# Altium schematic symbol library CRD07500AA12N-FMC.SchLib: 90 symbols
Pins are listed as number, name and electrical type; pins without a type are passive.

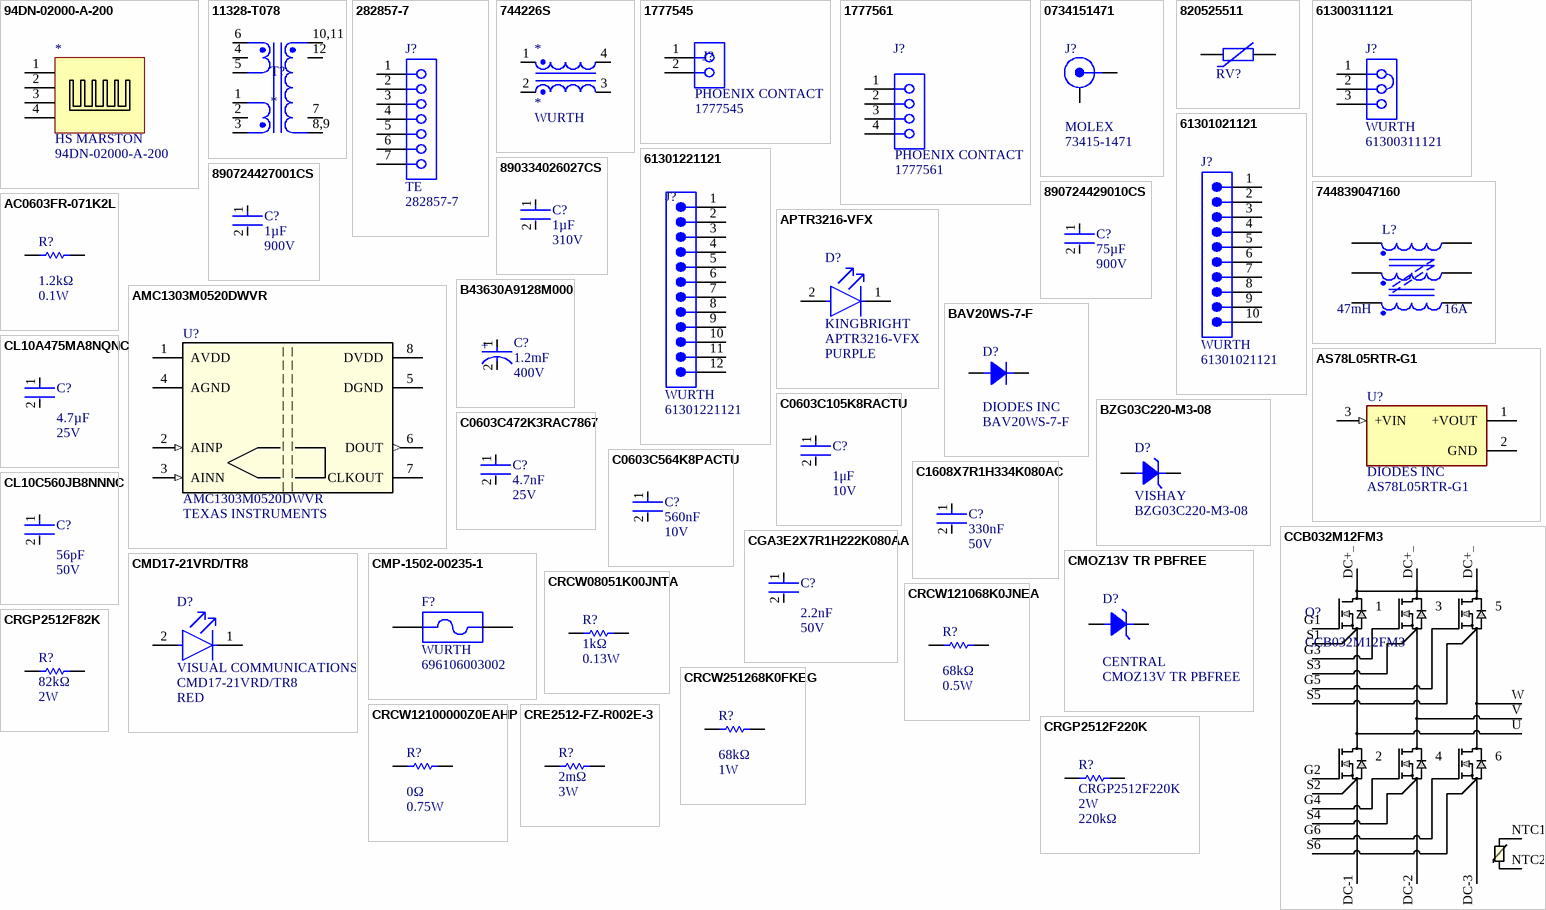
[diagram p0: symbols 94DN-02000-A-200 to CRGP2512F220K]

## 94DN-02000-A-200
designator *  Manufacturer: HS MARSTON  (hidden comment: 94DN-02000-A-200)
Heat Sink, Extruded Range - 4, Black Anodized, 0.7 C/w, 40 Mm, 123 Mm, 200 Mm Rohs Compliant: Yes; Natural Thermal Resistance: 0.7°C/W
footprint 94DN-02000-A-200
pins: 1, 2, 3, 4

## 11328-T078
designator T?
Sumida 11328-T078 flyback transformer / 600V, 670uH primary / 8:1:1
footprint 11328-T078 (Sumida 11328-T078 Flyback transformer)
pins: 1 P1, 2 NC1, 3 P1*, 4 NC0, 5 P0, 6 P0*, 7 NC2, 8,9 S, 10,11 S*, 12 NC3

## 282857-7
designator J?  Manufacturer: TE  (hidden comment: 282857-7)
Conn Terminal Block 7 POS 5.08mm Solder ST Thru-Hole; Plating: Brass; Current Rating: 24A; Voltage Rating: 300V; Number of Positions: 7; Number of Levels: 1; Connector Type: Receptacle; Closed End: No (Without); Interlock: Yes (With); Wire Gauge (Max): 30AWG; Thread Size: M3; Tail Length: 3.5mm
footprint TE_282857-7
pins: 1, 2, 3, 4, 5, 6, 7

## 744226S
designator *  Manufacturer Print: WURTH
Common Mode Chokes Dual 10uH 920Ohm 1kHz 1.6A 80mOhm DCR SMD T/R; Manufacturer: WURTH ELECTRONIK; Manufacturer Part Number: 744226S; Tolerance: 30%; Voltage Rating: 80V; Resistance: 80mR; Impedance: 920R; Number of Lines: 2
footprint WE-SL2 (SMD Inductor, 4-Leads, Body 6.3 x 9.5 mm)
pins: 1, 2, 3, 4

## 1777545
designator J?  Manufacturer: PHOENIX CONTACT  (hidden comment: 1777545)
Conn PC Terminal Block 2 POS 6.35mm Solder ST Thru-Hole 41A Cardboard; Voltage Rating: 1kV; Voltage: 600V; Number of Levels: 1; Number of Positions Per Level: 2; Current: 30A; Gender: Male; Connector Type: Screw; Wire Gauge (Max): 30AWG; Wire Gauge (Min): 10AWG; Approvals: cULus,EAC
footprint 1777545
pins: 1, 2

## 1777561
designator J?  Manufacturer: PHOENIX CONTACT  (hidden comment: 1777561)
Conn Terminal Block 4 POS 6.35mm Solder ST Thru-Hole 41A; Number of Positions: 4; Voltage Rating: 1kV; Number of Levels: 1; Current: 30A; Voltage: 600V; Wire Gauge (Max): 30AWG; Wire Gauge (Min): 10AWG
footprint 1777561
pins: 1, 2, 3, 4

## 0734151471
designator J?  Manufacturer: MOLEX  Manufacturer Part Number: 73415-1471  (hidden comment: 0734151471)
Conn.; RF/Coaxial; MMCX; Jack; Vertical; PCB; 50 Ohms; Rt. Angle; Gold Plate; Body Material: Brass; Impedance: 50R; Connector Type: PCB,MMCX,Coaxial; Max Frequency: 6GHz; Gender: Female
footprint FP-73415-1471-MFG
pins: 1 CENTER, 2,3,4,5 SHIELD

## 820525511
designator RV?, comment 550VAC, 745VDC  (value not drawn)
WE-VD Disk Varistor, THT, 550VAC, 745VDC, 430pF; Manufacturer Part Number: 820525511; Manufacturer: Wurth Elektronik; Clamping Voltage: 1500V; Energy Absorption: 408J; Operating Voltage (AC): 550V; Operating Voltage (DC): 745V; Pitch: 3.4mm; Power Dissipation: 1W; (Reverse) Breakdown Voltage: 910V; (Reverse) Peak Pulse Current: 6500A
footprint D23W10.1H27P3.4
pins: 1, 2

## 61300311121
designator J?  Manufacturer: WURTH  (hidden comment: 61300311121)
CONN HEADER 3 POS 2.54; Number of Positions: 3; Gender: Male; Connector Type: Male Pin; Pitch: 0.1inch
footprint 61300311121 (Pin Header, pitch 2.54 mm, THT, Vertical, single row, 3p)
pins: 1, 2, 3

## 61301021121
designator J?  Manufacturer: WURTH  (hidden comment: 61301021121)
THT Vertical Pin Header WR-PHD, Pitch 2.54 mm, Dual Row, 10 pins; Current Rating: 3A; Voltage Rating: 250V; Insulation: Insulated; Number of Positions: 10; Insulation Resistance: 1GR; Gender: Male; Pitch: 2.54mm; Row Spacing: 0.1inch
footprint 61301021121 (Pin Header, pitch 2.54 mm, THT, Vertical, dual row, 10p)
pins: 1, 2, 3, 4, 5, 6, 7, 8, 9, 10

## 61301221121
designator J?  Manufacturer Print: WURTH  (hidden comment: 61301221121)
CONN HEADER VERT 12POS 2.54MM; Manufacturer: WURTH ELEKTRONIK; Number of Positions: 12; Gender: Male; Voltage Rating: 250V; Pitch: 0.1inch
footprint FP-61301221121-MFG
pins: 1, 2, 3, 4, 5, 6, 7, 8, 9, 10, 11, 12

## 744839047160
designator L?, comment Rated Current: 16A  (hidden comment: 47mH)
WE-TPB HV THT Three-Phase Common Mode Power Line Choke, Type 4XL, 47mH, 16A, 14mΩ; Manufacturer Part Number: 744839047160; Manufacturer: Wurth Elektronik; Insulation Test Voltage (AC): 3000V; Material: MnZn; Rated Voltage (AC): 760V
footprint WE-TPB HV_Type 4XL_744839047160 (Three-Phase Common Mode Power Line Choke, 6-Leads, body diameter 70mm)
pins: 1, 2, 3, 4, 5, 6

## 890334026027CS
designator C?  Capacitance: 1µF  Voltage Rating (AC): 310V  (hidden comment: 890334026027CS)
WCAP-FTXX Film Capacitor 1uF 310Vac; Manufacturer: Wurth Electronics; Dielectric Material: PP; Tolerance: 10%; Ratings: X2
footprint WCAP-FTXX_L26W11H20_CS (Film Capacitors, 26x11x20mm)
pins: 1, 2

## 890724427001CS
designator C?  Capacitance: 1µF  Rated Voltage (DC): 900V  (hidden comment: 890724427001CS)
WCAP-FTDB DC-Link Capacitor, THT, L32 x W9 x H18mm, 1µF, 900V; Manufacturer: WURTH; Dissipation Factor @1kHz: 0.09%; Insulation Resistance: 10GΩ; Pitch: 27.5mm; Rate of Voltage Rise: 70V/µs; Technical Reference: MDBP275105J900DCPP15020
footprint WCAP-FTDB_L32W9H18
pins: 1, 2

## 890724429010CS
designator C?, comment Capacitance: 75µF  Rated Voltage (DC): 900V  (hidden comment: 75µF, 900V)
WCAP-FTDB DC-Link Capacitor, THT, L57 x W45 x H65mm, 75µF, 900V; Manufacturer Part Number: 890724429010CS; Manufacturer: Wurth Elektronik; Dissipation Factor @1kHz: 0.31%; Insulation Resistance: 133.33MΩ; Pitch: 52.5mm; Rate of Voltage Rise: 15V/µs; Technical Reference: MDBP525756J900DCPP15040
footprint WCAP-FTDB_L57W45H65
pins: 1, 2

## AC0603FR-071K2L
designator R?  Resistance: 1.2kΩ  Power Rating: 0.1W  (hidden comment: AC0603FR-071K2L)
Res Thick Film 0603 1.2K Ohm 1% 0.1W(1/10W) ±100ppm/°C Pad SMD Automotive T/R; Manufacturer: YAGEO; Max Power Dissipation: 100mW; Voltage Rating: 50V
footprint FP-MCR03-IPC_B
pins: 1, 2

## AMC1303M0520DWVR
designator U?  Manufacturer: TEXAS INSTRUMENTS  (hidden comment: AMC1303M0520DWVR)
1-Channel Single ADC Delta-Sigma 20Msps 16-bit Serial CMOS 8-Pin SOIC T/R; Number of Inputs: 1
footprint DWV0008A
pins: 1 AVDD (power), 2 AINP (in), 3 AINN (in), 4 AGND (power), 5 DGND (power), 6 DOUT (out), 7 CLKOUT, 8 DVDD (power)

## APTR3216-VFX
designator D?  Manufacturer Print: KINGBRIGHT  Manufacturer Part Number: APTR3216-VFX  Color: PURPLE  (hidden comment: *)
3.2X1.6MM Purple SMD Led (X=0.19, Y=0.05), Rohs
footprint FP-APTR3216SECK-MFG
pins: 1 C, 2 A

## AS78L05RTR-G1
designator U?  Manufacturer: DIODES INC  (hidden comment: AS78L05RTR-G1)
100mA 5V Linear Voltage Regulator SOT89; Max Power Dissipation: 750mW; Dropout Voltage: 1.8V; Number of Outputs: 1; Max Input Voltage: 30V; Polarity: Positive; Quiescent Current: 3mA; Accuracy: 5%; Output Type: Fixed
footprint SOT-89_4P5X2P45_DIO
pins: 1 +VOUT (power), 2 GND (power), 3 +VIN (in)

## B43630A9128M000
designator C?  Capacitance: 1.2mF  Voltage Rating: 400V  (hidden comment: B43630A9128M000)
CAP ALUM 1200UF 20% 400V SNAP; Manufacturer: TDK EPCOS; Polarity: Polar; ESR (Equivalent Series Resistance): 100mR; Life (Hours): 2000Hour; Impedance: 170mR
footprint B43630A9128M000 (400V 1200uF)
pins: 1, 2

## BAV20WS-7-F
designator D?  Manufacturer: DIODES INC  (hidden comment: BAV20WS-7-F)
VR=150V IF=200mA Trr=50ns P=200mW; Type: DEV; Forward Current: 200mA; Reverse Recovery Time: 50ns; Max Repetitive Reverse Voltage (Vrrm): 200V; Element Configuration: Single; Max Reverse Current: 100nA; Forward Voltage: 1.25V; Peak Non-Repetitive Surge Current: 2.5A; Power Dissipation: 200mW; Polarity: Standard; Capacitance: 5pF; Max Reverse Voltage (DC): 150V
footprint SOD323_DIO
pins: 1, 2

## BZG03C220-M3-08
designator D?  Manufacturer: VISHAY  (hidden comment: BZG03C220-M3-08)
BZG03 Series 220 V 0.5 A 1.25 W Surface Mount Zener Diode - DO-214AC; Zener Voltage: 220V; Tolerance: 5.68%; Max Power Dissipation: 1.25W; Impedance: 750R
footprint FP-SMA-MFG
pins: 1 11, 2 12

## C0603C105K8RACTU
designator C?  Capacitance: 1μF  Voltage Rating (DC): 10V  (hidden comment: C0603C105K8RACTU)
Cap Ceramic 1uF 10V X7R 10% SMD 0603 125C T/R; Manufacturer: KEMET; Dissipation Factor: 5%
footprint FP-C0603C-CF-IPC_B
pins: 1, 2

## C0603C472K3RAC7867
designator C?  Capacitance: 4.7nF  Voltage Rating: 25V  (hidden comment: C0603C472K3RAC7867)
CAP CER 4700PF 25V 10% X7R 0603; Manufacturer: KEMET; Manufacturer Part Number: C0603C472K3RACTU; Dielectric Material: Ceramic; Value: 4.7nF
footprint FP-C0603C-CF-IPC_B
pins: 1, 2

## C0603C564K8PACTU
designator C?  Capacitance: 560nF  Voltage Rating (DC): 10V  (hidden comment: C0603C564K8PACTU)
C0603C 560nF Ceramic Multilayer Capacitor; 10 VDC; +85degC; X5R Dielec; +/-10%; Manufacturer: KEMET; Tolerance: 10%
footprint FP-C0603C-CF-IPC_B
pins: 1, 2

## C1608X7R1H334K080AC
designator C?  Capacitance: 330nF  Voltage: 50V  (hidden comment: C1608X7R1H334K080AC)
Multilayer Ceramic Capacitor, 0.33 uF, 50 V, ± 10%, X7R, 0603 [1608 Metric]; Manufacturer: TDK
footprint FP-C0603C-CF-IPC_B
pins: 1, 2

## CCB032M12FM3
designator Q?
No Description Available; Mfr_Name: Cree Wolfspeed; Type: DEV
footprint FM3_SIX-PACK_3PHASE_CRW
pins: DC+_1, DC+_2, DC+_3, DC-1, DC-2, DC-3, G1, G2, G3, G4, G5, G6, NTC1, NTC2, S1, S2, S3, S4, S5, S6, U, V, W

## CGA3E2X7R1H222K080AA
designator C?  Capacitance: 2.2nF  Voltage Rating: 50V  (hidden comment: CGA3E2X7R1H222K080AA)
CAP CER 2200PF 50V X7R 0603; Manufacturer: TDK; Tolerance: 10%; Value: 2.2nF
footprint FP-GCM188-0_1-IPC_A
pins: 1, 2

## CL10A475MA8NQNC
designator C?  Capacitance: 4.7µF  Voltage Rating: 25V  (hidden comment: CL10A475MA8NQNC)
CAP CER 4.7UF 25V X5R 0603; Manufacturer: Samsung; Tolerance: 20%
footprint FP-C0603C-CF-IPC_B
pins: 1, 2

## CL10C560JB8NNNC
designator C?  Capacitance: 56pF  Voltage Rating: 50V  (hidden comment: CL10C560JB8NNNC)
CAP CER 56PF 50V C0G/NP0 0603; Manufacturer: SAMSUNG; Material: Ceramic; Tolerance: 5%; Dielectric: C0G; Temperature Coefficient: 30ppm/°C
footprint FP-C0603C-CF-IPC_B
pins: 1, 2
1 alternate drawing of the same symbol

## CMD17-21VRD/TR8
designator D?  value RED  Manufacturer: VISUAL COMMUNICATIONS  Manufacturer Part Number: CMD17-21VRD/TR8  (hidden comment: *)
LED RED DIFFUSED 0805 SMD; Power Rating: 100mW; Luminous Intensity: 6mcd; Viewing Angle: 140°; Lens Style: Diffused,Tinted,Rectangular,Colored; Forward Current: 20mA; Forward Voltage: 2V; Wavelength: 640nm; Reverse Voltage (DC): 5V; Number of LEDs: 1
footprint FP-LTST-C171GKT-MFG-RED
pins: 1 C, 2 A

## CMOZ13V TR PBFREE
designator D?  Manufacturer: CENTRAL  (hidden comment: CMOZ13V TR PBFREE)
DIODE ZENER 13V 300MW SOD523; Description: Diode Zener Single 13V 5% 350mW 2-Pin SOD-523 T/R; Tolerance: 5%; Impedance: 30R
footprint DIODE_SOD-523_1P2XP8_CNS
pins: 1, 2

## CMP-1502-00235-1
designator F?, comment Manufacturer: WURTH  (hidden comment: 696106003002)
WR-FSH Fuse Holder Blocks Fuse Holder Blocks Clip Cover for PCB; Fuse Size: 5x20mm
footprint 696106003002 (FUSEHOLDER BLOCKS - PCB - CLIP COVER - THT)
pins: 1, 2

## CRCW08051K00JNTA
designator R?  Resistance: 1kΩ  Power Rating: 0.13W  (hidden comment: *)
Resistor, Thick Film Chip; 1 K Ohms; Case 0805; 0.125W; +/-5%; SMD; 200ppm/K; 150V; Manufacturer: Vishay Dale; Manufacturer Part Number: CRCW08051K00JNTA; Tolerance: 5%; Temperature Coefficient: 200ppm/°C; Max Power Dissipation: 125mW
footprint RESC2013X50X30LL20T20 (Chip Resistor, 2-Leads, Body 2.00x1.25mm, IPC High Density)
footprint RESC2013X50X30ML20T20 (Chip Resistor, 2-Leads, Body 2.00x1.25mm, IPC Low Density)
footprint RESC2013X50X30NL20T20 (Chip Resistor, 2-Leads, Body 2.00x1.25mm, IPC Medium Density)
pins: 1, 2

## CRCW121068K0JNEA
designator R?  Resistance: 68kΩ  Max Power Dissipation: 0.5W  (hidden comment: CRCW121068K0JNEA)
Res Thick Film 1210 68K Ohm 5% 1/2W ±200ppm/°C Molded SMD SMD Paper T/R; Manufacturer: VISHAY DALE; Power Rating: 500mW; Voltage Rating: 200V
footprint RESC3125X70X40LL20T20 (Chip Resistor, 2-Leads, Body 3.10x2.50mm, IPC High Density)
footprint RESC3125X70X40ML20T20 (Chip Resistor, 2-Leads, Body 3.10x2.50mm, IPC Low Density)
footprint RESC3125X70X40NL20T20 (Chip Resistor, 2-Leads, Body 3.10x2.50mm, IPC Medium Density)
pins: 1, 2

## CRCW251268K0FKEG
designator R?  Resistance: 68kΩ  Power Rating: 1W  (hidden comment: CRCW251268K0FKEG)
Res Thick Film 2512 68K Ohm 1% 1W ±100ppm/°C Molded SMD SMD Blister T/R; Manufacturer: VISHAY DALE; Voltage Rating (DC): 500V
footprint FP-RC2512-0_65-IPC_A
footprint FP-RC2512-0_65-IPC_B
footprint FP-RC2512-0_65-IPC_C
footprint FP-RC2512-0_65-MFG
pins: 1, 2

## CRCW12100000Z0EAHP
designator R?  Resistance: 0Ω  Power Rating: 0.75W  (hidden comment: CRCW12100000Z0EAHP)
RES SMD 0 OHM JUMPER 3/4W 1210; Manufacturer: VISHAY; Max Power Dissipation: 750mW
footprint RESC3125X70X40NL20T20 (Chip Resistor, 2-Leads, Body 3.10x2.50mm, IPC Medium Density)
pins: 1, 2

## CRE2512-FZ-R002E-3
designator R?  Resistance: 2mΩ  Power Rating: 3W  (hidden comment: CRE2512-FZ-R002E-3)
Res Thick Film 2512 0.002 Ohm 1% 3W ±50ppm/C Pad SMD Automotive T/R; Manufacturer: BOURNS; Temperature Coefficient: 75ppm/°C
footprint FP-RC2512-0_65-MFG
pins: 1, 2

## CRGP2512F82K
designator R?  value 82kΩ  Power: 2W  (hidden comment: CRGP2512F82K)
Res Thick Film 2512 82K Ohm 1% 2W ±100ppm/C Pad SMD T/R; Manufacturer: TE
footprint FP-CRGP2512-IPC_A
footprint FP-CRGP2512-IPC_B
footprint FP-CRGP2512-IPC_C
pins: 1, 2

## CRGP2512F220K
designator R?  Power Rating: 2W  Resistance: 220kΩ
CRGP2512 220KΩ 2W ±100ppm/°C 1% 500V; Manufacturer: TE; Tolerance: 0.01
footprint FP-CRGP2512-IPC_C
footprint FP-CRGP2512-IPC_A
footprint FP-CRGP2512-IPC_B
pins: 1, 2

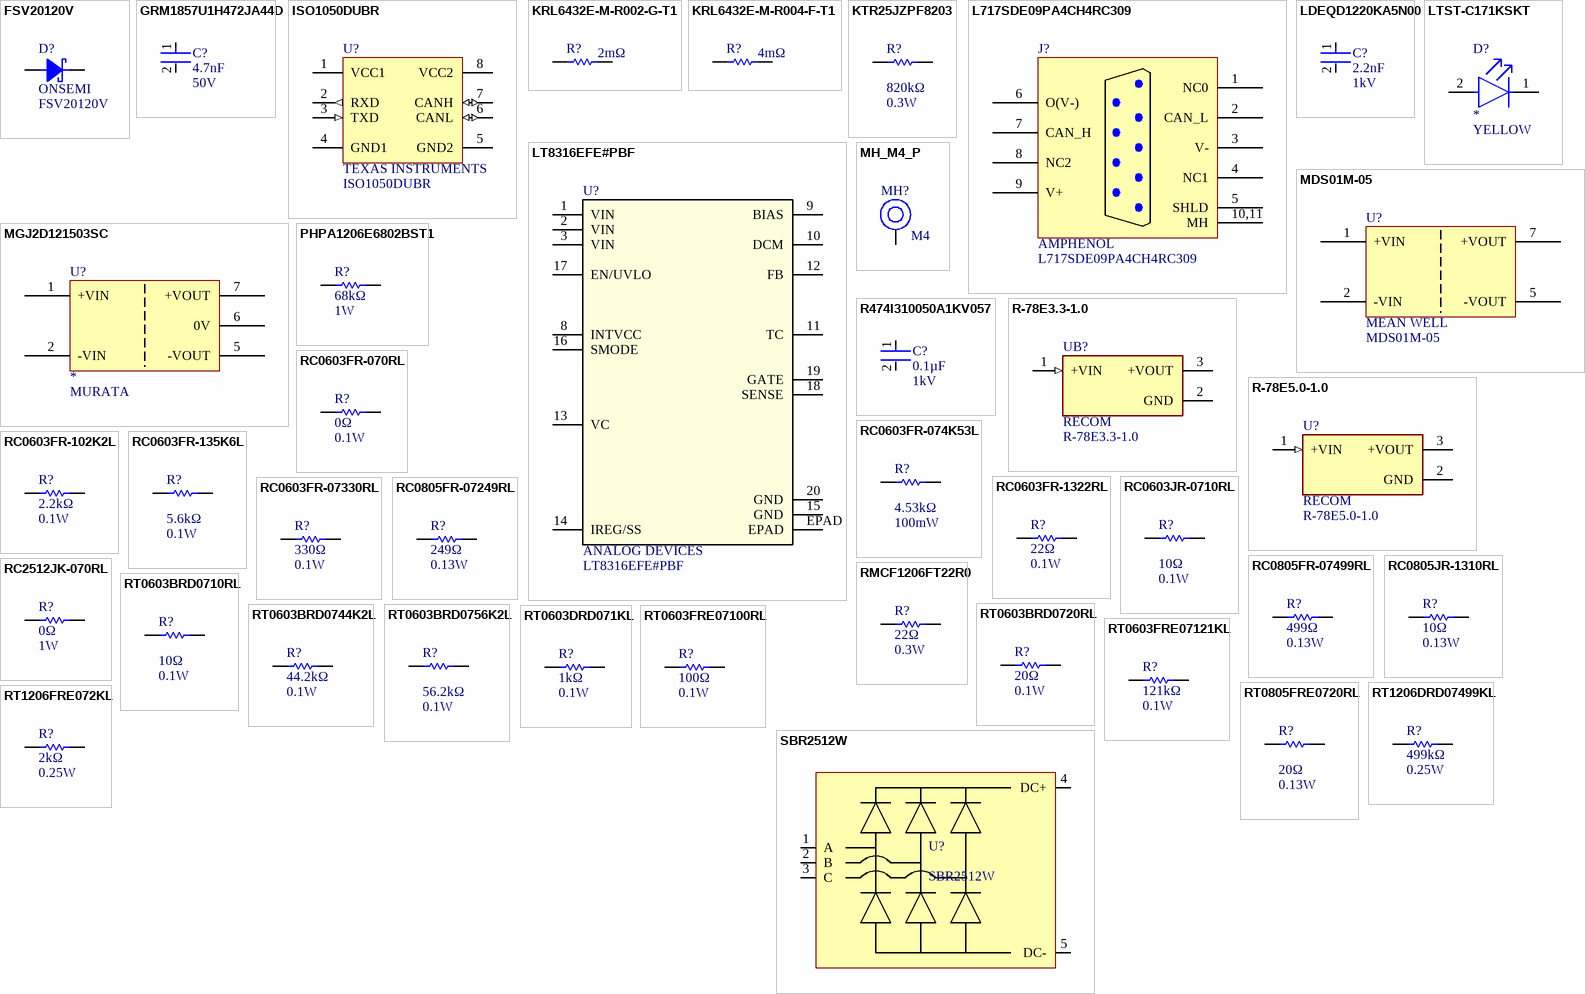
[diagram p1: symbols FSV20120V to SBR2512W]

## FSV20120V
designator D?  Manufacturer: ONSEMI  (hidden comment: FSV20120V)
Diode Schottky Rectifier 120V 20A 3-Pin TO-277 T/R; Element Configuration: Single; Max Forward Surge Current (Ifsm): 270A
footprint SOT_20100V_ONS
pins: 1,2, 3

## GRM1857U1H472JA44D
designator C?  Capacitance: 4.7nF  Voltage Rating (DC): 50V  (hidden comment: GRM1857U1H472JA44D)
Cap Ceramic 0.0047uF 50V U2J 5% SMD 0603 125°C Paper T/R; Manufacturer: MURATA
footprint FP-C0603C-CF-IPC_B
pins: 1, 2

## ISO1050DUBR
designator U?  Manufacturer: TEXAS INSTRUMENTS  (hidden comment: ISO1050DUBR)
Isolated CAN Transceiver, -55 to 105 degC, 8-pin SOP (DUB), Green (RoHS & no Sb/Br); Rating: Catalog; Isolated: Yes; Drivers Per Package: 1
footprint DUB0008A_M (SOP, 8-Leads, Body 6.7x9.6mm, Pitch 2.54mm, IPC Low Density)
footprint DUB0008A_L (SOP, 8-Leads, Body 6.7x9.6mm, Pitch 2.54mm, IPC High Density)
footprint DUB0008A_N (SOP, 8-Leads, Body 6.7x9.6mm, Pitch 2.54mm, IPC Medium Density)
pins: 1 VCC1 (power), 2 RXD (out), 3 TXD (in), 4 GND1 (power), 5 GND2 (power), 6 CANL (io), 7 CANH (io), 8 VCC2 (power)

## KRL6432E-M-R002-G-T1
designator R?  Resistance: 2mΩ  (hidden comment: KRL6432E-M-R002-G-T1)
Metal Foil Low Resistance Chip Resistor (long-side terminal), 2512, RoHS; Manufacturer: Susumu; Tolerance: 2%; Power Rating: 3W; Temperature Coefficient: 100ppm/°C
footprint RESC310X630X70N
pins: 1, 2

## KRL6432E-M-R004-F-T1
designator R?  Resistance: 4mΩ  (hidden comment: KRL6432E-M-R004-F-T1)
Metal Foil Low Resistance Chip Resistor (long-side terminal), 2512, RoHS; Manufacturer: Susumu; Tolerance: 1%; Power Rating: 3W; Temperature Coefficient: 50ppm/°C
footprint RESC310X630X70N
pins: 1, 2

## KTR25JZPF8203
designator R?  Resistance: 820kΩ  Max Power Dissipation: 0.3W  (hidden comment: KTR25JZPF8203)
Res Thick Film 1210 820K Ohm 1% 0.33W(1/3W) ±100ppm/C Pad SMD Automotive T/R; Manufacturer: ROHM; Temperature Coefficient: 100ppm/°C
footprint RESC3125X70X40LL20T20 (Chip Resistor, 2-Leads, Body 3.10x2.50mm, IPC High Density)
footprint RESC3125X70X40ML20T20 (Chip Resistor, 2-Leads, Body 3.10x2.50mm, IPC Low Density)
footprint RESC3125X70X40NL20T20 (Chip Resistor, 2-Leads, Body 3.10x2.50mm, IPC Medium Density)
pins: 1, 2

## L717SDE09PA4CH4RC309
designator J?  Manufacturer: AMPHENOL  (hidden comment: L717SDE09PA4CH4RC309)
CONN D-SUB PLUG 9POS R/A SLDR; Number of Terminals/Pins: 9; Connector Type: D-Sub,Plug; Voltage Rating: 250V; Current Rating: 5A; Number of Ports: 1; Pitch: 2.74mm
footprint L717SDE09PA4CH4RC309 (CONN D-SUB PLUG 9POS R/A SLDR)
pins: 1 NC0, 2 CAN_L, 3 V-, 4 NC1, 5 SHLD, 6 O(V-), 7 CAN_H, 8 NC2, 9 V+, 10,11 MH

## LDEQD1220KA5N00
designator C?  Capacitance: 2.2nF  Voltage Rating (DC): 1kV  (hidden comment: LDEQD1220KA5N00)
Cap Film 0.0022uF 1000V PEN 10% (6 X 5 X 2mm) Stacked 125C Automotive T/R; Manufacturer: KEMET; Dielectric Material: Polyester; Voltage Rating (AC): 250V
footprint CAP_LDE_QD_1220_KEM
pins: 1, 2

## LT8316EFE#PBF
designator U?  Manufacturer: ANALOG DEVICES  (hidden comment: LT8316EFE#PBF)
DC/DC Cntrlr Single-OUT Step Down/Flyback 142kHz Automotive 16-Pin TSSOP EP Tube
footprint TSSOP20_FE_BB(16)
pins: 1 VIN, 2 VIN, 3 VIN, 8 INTVCC, 9 BIAS, 10 DCM, 11 TC, 12 FB, 13 VC, 14 IREG/SS, 15 GND, 16 SMODE, 17 EN/UVLO, 18 SENSE, 19 GATE, 20 GND, EPAD

## LTST-C171KSKT
designator D?  Color Print: YELLOW
LED YELLOW CLEAR 0805 SMD; Manufacturer: Vishay Lite-On; Manufacturer Part Number: LTST-C171KSKT; Lens Color: Colorless; Number of LEDs: 1; Reverse Voltage: 5V; Viewing Angle: 130°; Lens Style: Diffused,Colorless,Rectangular,Clear; Luminous Intensity: 50mcd; Forward Voltage: 2V; Dominant Wavelength: 587nm; Test Current: 20mA; Wavelength: 588nm; Forward Current: 30mA; Max Power Dissipation: 75mW
footprint FP-LTST-C171GKT-MFG-YELLOW
pins: 1 C, 2 A

## MDS01M-05
designator U?  Manufacturer: MEAN WELL  (hidden comment: MDS01M-05)
Module DC-DC 1-OUT 5V 20mA to 200mA 1W Through Hole 5-Pin SIP
footprint MDS01M-05
pins: 1 +VIN, 2 -VIN, 5 -VOUT, 7 +VOUT

## MGJ2D121503SC
designator U?  Manufacturer Print: MURATA
DC DC CONVERTER 15V -3V 1.7W; Manufacturer Part Number: MGJ2D121503SC
footprint MGJ2D121509SC
pins: 1 +VIN, 2 -VIN, 5 -VOUT, 6 0V, 7 +VOUT

## MH_M4_P
designator MH?  Size: M4  (hidden comment: *)
footprint MH_M4_P (M4 plated mounting hole)
pins: 1

## PHPA1206E6802BST1
designator R?  Resistance: 68kΩ  Power: 1W  (hidden comment: PHPA1206E6802BST1)
THIN FILM RES SMD 68K OHM 0.1% 1; Manufacturer: VISHAY
footprint RESC3216X65X50NL15T25 (Chip Resistor, 2-Leads, Body 3.20x1.60mm, IPC Medium Density)
pins: 1, 2

## R474I310050A1KV057
designator C?  Capacitance: 0.1µF  Voltage: 1kV  (hidden comment: R474I310050A1KV057)
0.1uF, 1KVDC, X1 rated; Manufacturer: KEMET
footprint R474I310050A1KV057 (0.1uF 1KVDC X1)
pins: 1, 2

## R-78E3.3-1.0
designator UB?  Manufacturer: RECOM  (hidden comment: R-78E3.3-1.0)
DC DC CONVERTER 3.3V 3W; Number of Outputs: 1; Min Input Voltage: 8V; Max Input Voltage: 28V; Max Output Current: 1A; Efficiency: 91%; Max Output Power: 3.3W; Min Input Voltage (DC): 7V
footprint CONV_R-78E3.3-1.0
pins: 1 +VIN (in), 2 GND (power), 3 +VOUT (power)

## R-78E5.0-1.0
designator U?  Manufacturer: RECOM  (hidden comment: R-78E5.0-1.0)
DC DC CONVERTER 5V 5W; Number of Outputs: 1; Min Input Voltage: 8V; Max Input Voltage: 28V; Max Output Current: 1A; Efficiency: 91%
footprint CONV_R-78E5.0-1.0
pins: 1 +VIN (in), 2 GND (power), 3 +VOUT (power)

## RC0603FR-070RL
designator R?  Resistance: 0Ω  Power Rating: 0.1W  (hidden comment: RC0603FR-070RL)
RC Series 0603 0.1 W 0 Ohm Jumper Surface Mount Thick Film Chip Resistor; Manufacturer: YAGEO; Tolerance: 1%; Voltage Rating (DC): 50V; Max Power Dissipation: 100mW; Temperature Coefficient: 200ppm/°C; Current Rating: 1A; Working Voltage: 75V
footprint FP-MCR03-IPC_B
pins: 1, 2

## RC0603FR-074K53L
designator R?  Resistance: 4.53kΩ  Power Rating: 100mW  (hidden comment: RC0603FR-074K53L)
Res Thick Film 0603 4.53K Ohm 1% 0.1W(1/10W) ±100ppm/C Pad SMD T/R; Manufacturer: YAGEO; Temperature Coefficient: 100ppm/°C; Voltage Rating: 50V
footprint FP-MCR03-IPC_B
pins: 1, 2

## RC0603FR-102K2L
designator R?  Resistance: 2.2kΩ  Power Rating: 0.1W  (hidden comment: RC0603FR-102K2L)
Res Thick Film 0603 2.2K Ohm 1% 1/10W 100ppm/C Molded SMD SMD Paper T/R; Manufacturer: YAGEO; Temperature Coefficient: 100ppm/°C; Voltage Rating (DC): 50V
footprint FP-MCR03-IPC_B
pins: 1, 2

## RC0603FR-135K6L
designator R?  Resistance: 5.6kΩ  Power Rating: 0.1W  (hidden comment: RC0603FR-135K6L)
Res Thick Film 0603 5.6K Ohm 1% 1/10W ±100ppm/°C Molded SMD Paper T/R; Manufacturer: YAGEO; Voltage Rating: 50V
footprint FP-MCR03-IPC_B
pins: 1, 2

## RC0603FR-1322RL
designator R?  Resistance: 22Ω  Power Rating: 0.1W  (hidden comment: RC0603FR-1322RL)
Res Thick Film 0603 22 Ohm 1% 1/10W ±100ppm/°C SMD Paper T/R; Manufacturer: Yageo; Voltage Rating: 50V
footprint FP-MCR03-IPC_B
pins: 1, 2

## RC0603FR-07330RL
designator R?  Resistance: 330Ω  Max Power Dissipation: 0.1W  (hidden comment: RC0603FR-07330RL)
YAGEO (PHYCOMP) - RC0603FR-07330RL - RES, THICK FILM, 330R, 1%, 0.1W, 0603; Temperature Coefficient: 100ppm/°C; Power Rating: 100mW; Voltage Rating: 50V
footprint FP-MCR03-IPC_B
pins: 1, 2

## RC0603JR-0710RL
designator R?  Resistance: 10Ω  Max Power Dissipation: 0.1W  (hidden comment: RC0603JR-0710RL)
Res General Purpose Thick Film 0603 10 Ohm 5% 1/10W ±200ppm/°C Molded SMD Paper T/R; Manufacturer: YAGEO; Power Rating: 100mW; Voltage Rating: 50V
footprint FP-MCR03-IPC_B
pins: 1, 2

## RC0805FR-07249RL
designator R?  Resistance: 249Ω  Power Rating: 0.13W  (hidden comment: *)
RES 249 OHM 1% 1/8W 0805; Manufacturer: YAGEO; Manufacturer Part Number: RC0805FR-07249RL; Voltage Rating: 150V; Max Power Dissipation: 125mW; Temperature Coefficient: 100ppm/°C; Value: 249Ω
footprint FP-MCR10-IPC_A
pins: 1, 2

## RC0805FR-07499RL
designator R?  Resistance: 499Ω  Max Power Dissipation: 0.13W  (hidden comment: *)
RES 499 OHM 1% 1/8W 0805; Manufacturer: YAGEO; Manufacturer Part Number: RC0805FR-07499RL; Power Rating: 125mW; Voltage Rating: 150V; Temperature Coefficient: 100ppm/°C; Value: 499Ω
footprint FP-MCR10-IPC_A
pins: 1, 2

## RC0805JR-1310RL
designator R?  Resistance: 10Ω  Power Rating: 0.13W  (hidden comment: RC0805JR-1310RL)
Res Thick Film 0805 10 Ohm 5% 1/8W ±200ppm/°C Molded SMD Paper T/R; Manufacturer: YAGEO; Voltage Rating: 150V
footprint RESC2013X60X35LL10T20 (Chip Resistor, 2-Leads, Body 2.00x1.25mm, IPC High Density)
footprint RESC2013X60X35ML10T20 (Chip Resistor, 2-Leads, Body 2.00x1.25mm, IPC Low Density)
footprint RESC2013X60X35NL10T20 (Chip Resistor, 2-Leads, Body 2.00x1.25mm, IPC Medium Density)
pins: 1, 2

## RC2512JK-070RL
designator R?  Resistance: 0Ω  Max Power Dissipation: 1W  (hidden comment: RC2512JK-070RL)
RES SMD 0 OHM JUMPER 1W 2512; Manufacturer: YAGEO; Tolerance: 5%; Temperature Coefficient: 200ppm/°C; Voltage Rating: 200V
footprint FP-RC2512-0_65-IPC_A
footprint FP-RC2512-0_65-IPC_B
footprint FP-RC2512-0_65-IPC_C
footprint FP-RC2512-0_65-MFG
pins: 1, 2

## RMCF1206FT22R0
designator R?  Resistance: 22Ω  Max Power Dissipation: 0.3W  (hidden comment: RMCF1206FT22R0)
Res Thick Film 1206 22 Ohm 1% 1/4W ±100ppm/°C Molded SMD SMD Paper T/R; Manufacturer: Stackpole Electronics
footprint FP-CSR1206-IPC_A
footprint FP-CSR1206-IPC_B
footprint FP-CSR1206-IPC_C
footprint FP-CSR1206-MFG
pins: 1, 2

## RT0603BRD0710RL
designator R?  Resistance: 10Ω  Max Power Dissipation: 0.1W  (hidden comment: RT0603BRD0710RL)
Res Thin Film 0603 10 Ohm 0.1% 0.1W(1/10W) ±25ppm/C Pad SMD T/R; Manufacturer: Yageo; Temperature Coefficient: 25ppm/°C; Power Rating: 100mW; Voltage Rating: 75V
footprint FP-MCR03-IPC_B
pins: 1, 2

## RT0603BRD0720RL
designator R?  Resistance: 20Ω  Power Rating: 0.1W  (hidden comment: RT0603BRD0720RL)
Res Thin Film 0603 20 Ohm 0.1% 1/10W ±25ppm/°C Molded SMD SMD Paper T/R; Manufacturer: YAGEO; Max Power Dissipation: 100mW; Voltage Rating: 75V; Voltage Rating (DC): 50V
footprint FP-MCR03-IPC_B
pins: 1, 2

## RT0603BRD0744K2L
designator R?  Resistance: 44.2kΩ  Max Power Dissipation: 0.1W  (hidden comment: RT0603BRD0744K2L)
Res High Precision Thin Film 0603 44.2k Ohm 0.1% 1/10W ±25ppm/°C Molded Paper T/R; Manufacturer: YAGEO; Power Rating: 100mW; Voltage Rating (DC): 50V; Voltage Rating: 75V
footprint FP-MCR03-IPC_B
pins: 1, 2

## RT0603BRD0756K2L
designator R?  Resistance: 56.2kΩ  Power Rating: 0.1W  (hidden comment: RT0603BRD0756K2L)
Res Thin Film 0603 56.2K Ohm 0.1% 1/10W ±25ppm/°C Molded SMD SMD Paper T/R; Manufacturer: YAGEO; Max Power Dissipation: 100mW; Voltage Rating: 75V; Voltage Rating (DC): 50V
footprint FP-MCR03-IPC_B
pins: 1, 2

## RT0603DRD071KL
designator R?  Resistance: 1kΩ  Power Rating: 0.1W  (hidden comment: RT0603DRD071KL)
Res Thin Film 0603 1K Ohm 0.5% 1/10W ±25ppm/°C Molded SMD SMD Paper T/R; Manufacturer: YAGEO; Max Power Dissipation: 100mW; Voltage Rating (DC): 50V; Voltage Rating: 75V
footprint FP-MCR03-IPC_B
pins: 1, 2

## RT0603FRE07100RL
designator R?  Resistance: 100Ω  Power Rating: 0.1W  (hidden comment: RT0603FRE07100RL)
RES SMD 100 OHM 1% 1/10W 0603; Manufacturer: YAGEO; Temperature Coefficient: 50ppm/°C; Voltage Rating: 75V; Max Power Dissipation: 100mW
footprint FP-MCR03-IPC_B
pins: 1, 2

## RT0603FRE07121KL
designator R?  Resistance: 121kΩ  Power Rating: 0.1W  (hidden comment: RT0603FRE07121KL)
Res Thin Film 0603 121K Ohm 1% 1/10W ±50ppm/°C Molded SMD SMD Paper T/R; Manufacturer: YAGEO; Voltage Rating (DC): 50V; Voltage Rating: 75V; Max Power Dissipation: 100mW
footprint FP-MCR03-IPC_B
pins: 1, 2

## RT0805FRE0720RL
designator R?  Resistance: 20Ω  Max Power Dissipation: 0.13W  (hidden comment: RT0805FRE0720RL)
Res Thin Film 0805 20 Ohm 1% 1/8W ±50ppm/°C Molded SMD SMD Paper T/R; Manufacturer: YAGEO; Power Rating: 125mW; Voltage Rating: 150V
footprint RESC2013X60X35LL10T20 (Chip Resistor, 2-Leads, Body 2.00x1.25mm, IPC High Density)
footprint RESC2013X60X35ML10T20 (Chip Resistor, 2-Leads, Body 2.00x1.25mm, IPC Low Density)
footprint RESC2013X60X35NL10T20 (Chip Resistor, 2-Leads, Body 2.00x1.25mm, IPC Medium Density)
pins: 1, 2

## RT1206DRD07499KL
designator R?  Resistance: 499kΩ  Max Power Dissipation: 0.25W  (hidden comment: RT1206DRD07499KL)
Res Thin Film 1206 499K Ohm 0.5% 0.25W(1/4W) ±25ppm/C Pad SMD T/R; Manufacturer: YAGEO; Temperature Coefficient: 25ppm/°C; Voltage Rating (DC): 200V
footprint FP-CSR1206-IPC_A
footprint FP-CSR1206-IPC_B
footprint FP-CSR1206-IPC_C
footprint FP-CSR1206-MFG
pins: 1, 2

## RT1206FRE072KL
designator R?  Resistance: 2kΩ  Max Power Dissipation: 0.25W  (hidden comment: RT1206FRE072KL)
Res Thin Film 1206 2K Ohm 1% 1/4W ±50ppm/°C Molded SMD SMD Paper T/R; Manufacturer: YAGEO; Power Rating: 250mW; Voltage Rating: 200V
footprint FP-CSR1206-IPC_A
footprint FP-CSR1206-IPC_B
footprint FP-CSR1206-IPC_C
footprint FP-CSR1206-MFG
pins: 1, 2

## SBR2512W
designator U?
BRIDGE RECT 3P 1.2KV 25A
footprint SBR2512W (3P diode bridge 1200V 25A)
pins: 1 A, 2 B, 3 C, 4 DC+, 5 DC-

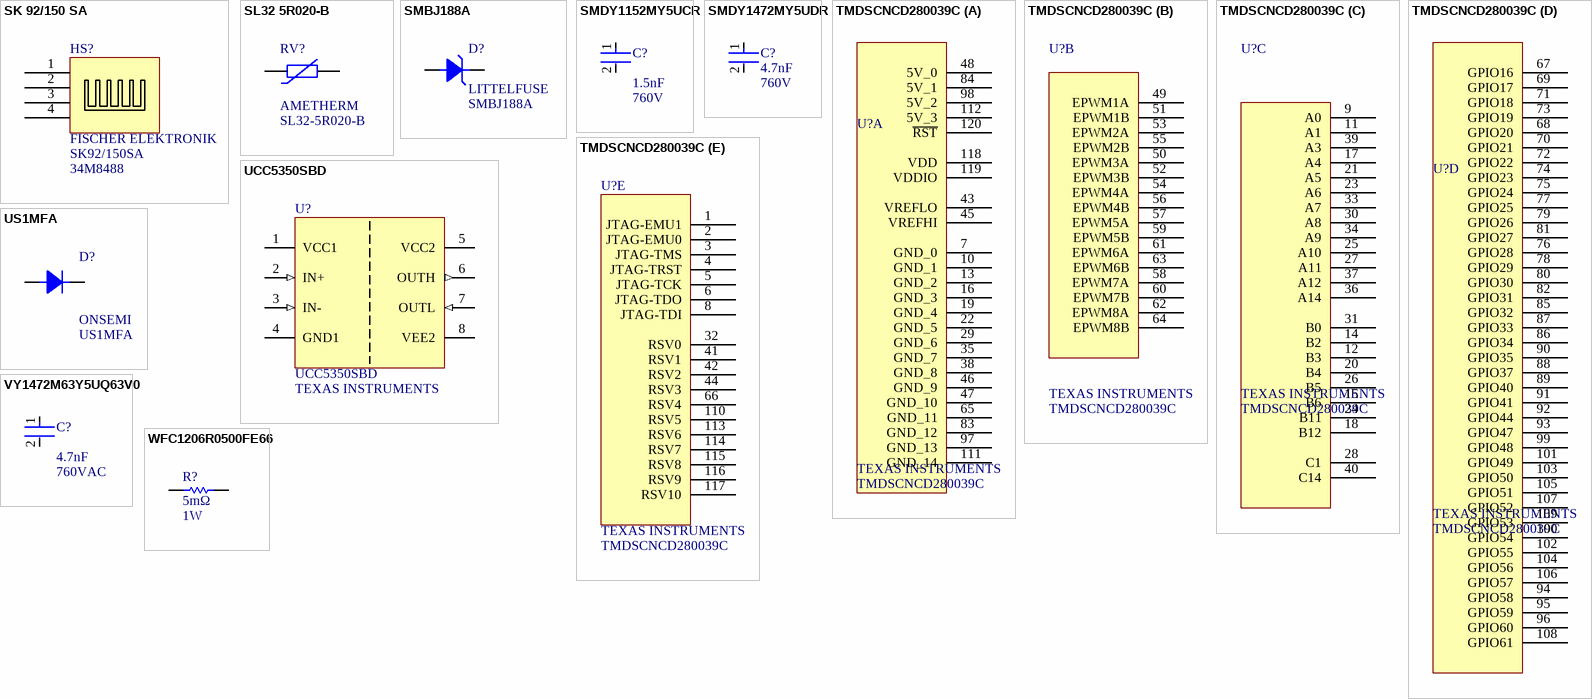
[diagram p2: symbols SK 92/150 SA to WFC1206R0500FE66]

## SK 92/150 SA
designator HS?  Manufacturer: FISCHER ELEKTRONIK  Manufacturer Part Number: SK92/150SA  Supplier Part Number 1: 34M8488  (hidden comment: SK 92/150 SA)
Heat Sink, Standard Extruded, Black Anodized, 1.2 C/w, 40 Mm, 100 Mm, 150 Mm Rohs Compliant: Yes; Natural Thermal Resistance: 1.2°C/W
footprint SK 92 150 SA
pins: 1, 2, 3, 4

## SL32 5R020-B
designator RV?  Manufacturer: AMETHERM  Manufacturer Part Number: SL32-5R020-B  (hidden comment: SL32 5R020-B)
Inrush Current Limiters 32mm 5ohms 20A KINK INRSH CURR LIMITER; Resistance: 5R; Tolerance: 20%; Dissipation Factor: 45.4%; Lead Diameter: 1mm; Approvals: CSA,UR
footprint SL22 10008-B-Footprint-1
pins: 1, 2

## SMBJ188A
designator D?  Manufacturer: LITTELFUSE  (hidden comment: SMBJ188A)
Surface Mount Transient Voltage Suppressor; Mfr_Name: Littelfuse Inc; Type: DEV; Peak Pulse Power: 600W; Clamping Voltage: 328V; Max Surge Current: 2A; Number of Channels: 1; Polarity: Unidirectional; Operating Supply Voltage: 188V; Breakdown Voltage: 209V; Power Line Protection: No; Diode Type: ZENER
footprint SMBJSeries_LTF
pins: 1 11, 2 12

## SMDY1152MY5UCR
designator C?  value 1.5nF  Voltage: 760V  (hidden comment: SMDY1152MY5UCR)
SMDY1 X760Y500VAC 1500PF 20% Y5U; Manufacturer: VISHAY; Description: Ceramic Suppression Cap, 1500PF, X1/Y1 Rohs Compliant: Yes
footprint CAP_MY5UCR_VIS
pins: 1, 2

## SMDY1472MY5UDR
designator C?  Capacitance: 4.7nF  Voltage: 760V  (hidden comment: SMDY1472MY5UDR)
Ceramic Suppression Cap, 4700PF, X1/Y1 Rohs Compliant: Yes; Manufacturer: Vishay
footprint CAP_MY5UCR_VIS
pins: 1, 2

## TMDSCNCD280039C
designator U?  Manufacturer: TEXAS INSTRUMENTS  Manufacturer Part Number: TMDSCNCD280039C  (hidden comment: *)
EVAL BOARD FOR TMS320F280039C
footprint TMDSCNCD280039C
part A pins: 7 GND_0, 10 GND_1, 13 GND_2, 16 GND_3, 19 GND_4, 22 GND_5, 29 GND_6, 35 GND_7, 38 GND_8, 43 VREFLO, 45 VREFHI, 46 GND_9, 47 GND_10, 48 5V_0, 65 GND_11, 83 GND_12, 84 5V_1, 97 GND_13, 98 5V_2, 111 GND_14, 112 5V_3, 118 VDD, 119 VDDIO, 120 ~{RST}
part B pins: 49 EPWM1A, 50 EPWM3A, 51 EPWM1B, 52 EPWM3B, 53 EPWM2A, 54 EPWM4A, 55 EPWM2B, 56 EPWM4B, 57 EPWM5A, 58 EPWM7A, 59 EPWM5B, 60 EPWM7B, 61 EPWM6A, 62 EPWM8A, 63 EPWM6B, 64 EPWM8B
part C pins: 9 A0, 11 A1, 12 B3, 14 B2, 15 B6, 17 A4, 18 B12, 20 B4, 21 A5, 23 A6, 24 B11, 25 A10, 26 B5, 27 A11, 28 C1, 30 A8, 31 B0, 33 A7, 34 A9, 36 A14, 37 A12, 39 A3, 40 C14
part D pins: 67 GPIO16, 68 GPIO20, 69 GPIO17, 70 GPIO21, 71 GPIO18, 72 GPIO22, 73 GPIO19, 74 GPIO23, 75 GPIO24, 76 GPIO28, 77 GPIO25, 78 GPIO29, 79 GPIO26, 80 GPIO30, 81 GPIO27, 82 GPIO31, 85 GPIO32, 86 GPIO34, 87 GPIO33, 88 GPIO37, 89 GPIO40, 90 GPIO35, 91 GPIO41, 92 GPIO44, 93 GPIO47, 94 GPIO58, 95 GPIO59, 96 GPIO60, 99 GPIO48, 100 GPIO54, 101 GPIO49, 102 GPIO55, 103 GPIO50, 104 GPIO56, 105 GPIO51, 106 GPIO57, 107 GPIO52, 108 GPIO61, 109 GPIO53
part E pins: 1 JTAG-EMU1, 2 JTAG-EMU0, 3 JTAG-TMS, 4 JTAG-TRST, 5 JTAG-TCK, 6 JTAG-TDO, 8 JTAG-TDI, 32 RSV0, 41 RSV1, 42 RSV2, 44 RSV3, 66 RSV4, 110 RSV5, 113 RSV6, 114 RSV7, 115 RSV8, 116 RSV9, 117 RSV10

## UCC5350SBD
designator U?  Manufacturer Print: TEXAS INSTRUMENTS
5A/5A, 3-KVRMS SINGLE-CHANNEL IS; Class: U; Working Voltage: 990V; Number of Channels: 1
footprint D0008B_HV
pins: 1 VCC1 (power), 2 IN+ (in), 3 IN- (in), 4 GND1 (power), 5 VCC2 (power), 6 OUTH (out), 7 OUTL (in), 8 VEE2 (power)

## US1MFA
designator D?  Manufacturer: ONSEMI  (hidden comment: US1MFA)
DIODE GEN PURP 1KV 1A SOD123FA; Peak Reverse Current: 5uA; Max Surge Forward Current: 30A; Automotive Grade: Grade 0; Max Junction Temp: +150°C; Max Repetitive Reverse Voltage: 1000V; Capacitance: 15pF; Value: 15pF
footprint FP-425AB-MFG
pins: 1 C, 2 A

## VY1472M63Y5UQ63V0
designator C?  Capacitance: 4.7nF  Voltage: 760VAC  (hidden comment: VY1472M63Y5UQ63V0)
Cap Ceramic 0.0047uF 1500V Y5U 20% Through Hole 10mm 125°C Bulk; Manufacturer: VISHAY; Manufacturer Part Number: VY1472M61Y5UC63V0; Dissipation Factor: 2.5%; Lead/Base Style: Kinked; Ratings: X1,Y1
footprint VY1472M63Y5UQ63V0 (4700pF 760VAC Y1)
pins: 1, 2

## WFC1206R0500FE66
designator R?  value 5mΩ  Power: 1W  (hidden comment: WFC1206R0500FE66)
Res 0.05 Ohm 1.0 W 1% 1206 SMD; Manufacturer: VISHAY DALE
footprint FP-CSR1206-IPC_A
footprint FP-CSR1206-IPC_B
footprint FP-CSR1206-IPC_C
footprint FP-CSR1206-MFG
pins: 1, 2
